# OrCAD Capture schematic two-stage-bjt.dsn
size A; title: Two-Stage BJT Amplifier
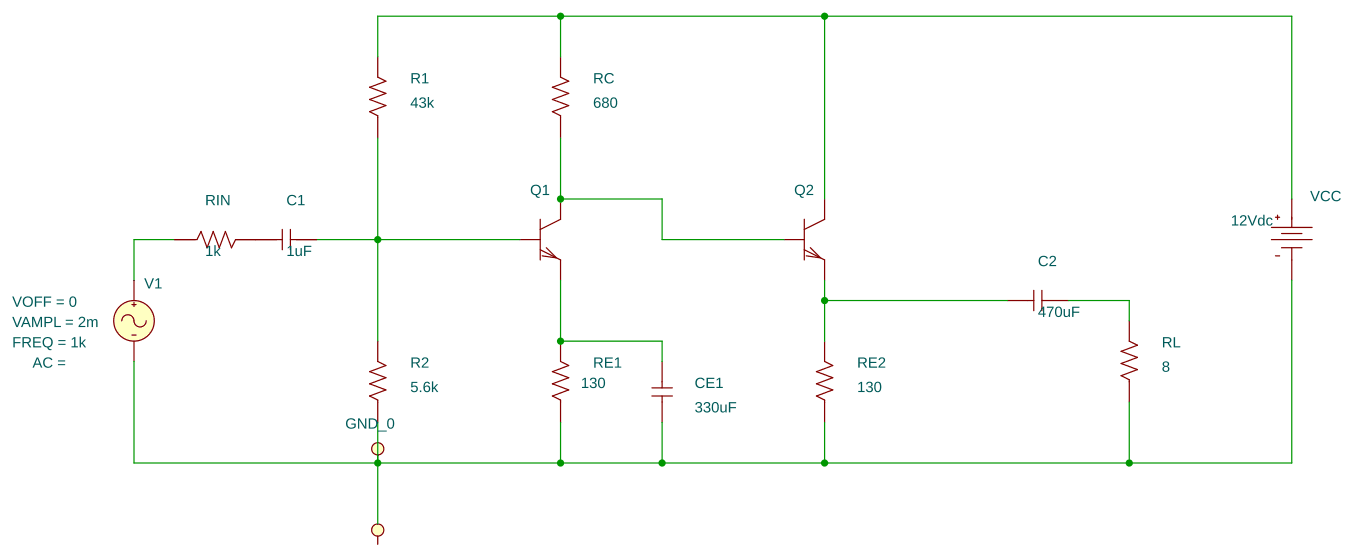
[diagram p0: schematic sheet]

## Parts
C1  1uF  [cap196]
C2  470uF  [cap196]
CE1  330uF  [cap196]
Q1  QbreakN
Q2  QbreakN
R1  43k  [AXRC05]
R2  5.6k  [AXRC05]
RC  680  [AXRC05]
RE1  130  [AXRC05]
RE2  130  [AXRC05]
RIN  1k  [AXRC05]
RL  8  [AXRC05]
V1  VSIN
VCC  VDC

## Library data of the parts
C1 C2 CE1 = C
Q1 Q2 = QbreakN
R1 R2 RC RE1 RE2 RIN RL = R
V1 = VSIN: FREQ: 1k; VAMPL: 2m; VOFF: 0
VCC = VDC: DC: 12Vdc

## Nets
0: CE1.1 R2.1 RE1.1 RE2.1 RL.1 V1.2(-) VCC.1(-)
N15122: Q2.1(c) R1.2 RC.2 VCC.0(+)
N15184: C1.2 Q1.0(b) R1.1 R2.2
N15188: Q1.1(c) Q2.0(b) RC.1
N15292: RIN.1 V1.1(+)
N15330: CE1.2 Q1.2(e) RE1.2
N15798: C2.1 Q2.2(e) RE2.2
N16231: C2.2 RL.2
N22982: C1.1 RIN.2
